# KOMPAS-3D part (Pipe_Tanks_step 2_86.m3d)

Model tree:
1. X Axis
2. Y Axis
3. Z Axis  (labels: Pipe Dn 50; Valve Dy 50)
     Òîëùèíà ñòåíêè 1 = 1

Referenced files in C:\Documents and Settings\kashirsky\Мои документы\Camtasia Studio\Pipelines3D\Tanks\: Tanks_step 4.a3d
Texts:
  Pipe Dn 50
  Steel ASTM A295
  Three Point Plane
  Plane at Angle
  Line and Point Plane
  Axis through Two Vertices
  Axis of Feature
  Axis of Conical Surface
  Axis through Edge
  Trim by Surface
  Trim by Sketch
  Feature with No History
  Intersection Axis of Two Planes
  Two Line Plane
  Line and Face Plane
  Bend by line
  Hole in sheet body
  Cut in sheet body
  Point in CM
  Linear Dimension from Line to Point
  Surface Finish Symbol
  Geometric Tolerance Symbol
  Leader #1
  Leader #2
  Leader #3
  Shape Deviations and Datum
  Node point number
  Mark of coordination axis
  Node point designation
  Mark/Reference designation with leader
  Mark/reference designation on line
  Mark/Reference designation without leader
  Valve Dy 50
  Plane of section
